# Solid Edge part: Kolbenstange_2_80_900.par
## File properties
Username: ahadarics
Dokumentum tartalom típus: 0
Author: ahadarics
Last saved by: ahadarics
Revision: 92
Sűrűség: 0,000 kg/m^3
Pontosság: 0,990
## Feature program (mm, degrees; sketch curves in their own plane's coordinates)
base feature "unnamed BaseFeature 1"
thread "unnamed Thread 1"
chamfer "Letörés_1"  SetBackValue2 = 20 deg
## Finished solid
Body 1: solid body, 19 faces, 31 edges, 16 vertices.
  Faces by surface: plane 8, cylinder 5, cone 3, torus 3
  Edges by curve: circle 18, line 8, curve on surface 3, ellipse 2
Bounding box of the edges (mm; curved faces can reach further): 80.000 x 80.000 x 1027.000, from (-40, -40, -76) to (40, 40, 951).
Cylindrical faces by radius (mm): R8.75 x1, R10 x1, R12.25 x1, R12.5 x1, R40 x1
Conical faces (half-angle, radius in mm at the cone's reference point): 20 deg R8.7989 x1, 30 deg R12.375 x1, 60 deg R9.375 x1
Toroidal faces (ring radius, tube radius in mm): R9.15 r0.4 x2, R10.45 r1.8 x1
Planar faces by outward normal: +x 1, +z 3, -x 1, -z 1, oblique 2
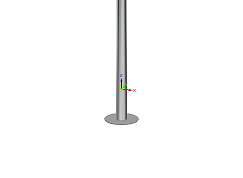
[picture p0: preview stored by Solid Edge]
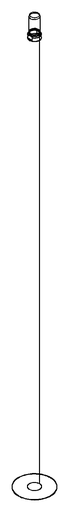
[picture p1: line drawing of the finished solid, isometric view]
